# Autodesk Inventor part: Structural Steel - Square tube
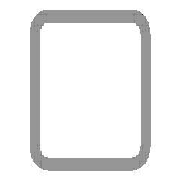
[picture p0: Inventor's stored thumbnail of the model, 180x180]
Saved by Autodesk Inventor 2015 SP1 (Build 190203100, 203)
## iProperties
_CCFamilyMember: 2
_CCFamilyDisplayName: ISO 4019 (Square) - Structural steels - Cold-formed, welded, structural hollow sections
_FrameMemberDoc: Frame Member File
_Version: 15.0.0
_GetPNFromCC: 1
Created: 2011-06
Part Number: Structural Steel - Square tube
Material: Stainless Steel
Document SubType Name: Modeling
Standard: ISO
Designer: Guilherme Augusto Franco de Souza
Standard Revision: Second edition 2001-09-01
Standards Organization: ISO
Language: en-US
Size Designation: 25x25x2
Categories: <MemberInstance><Categories><Category DisplayName="Structural Shapes" InternalName="089c4875-fa83-4c05-b084-43b9cc11f5ed" Mnemonic="GRDR"><CategoryParameter Dis
Stock Number: 25x25x2
Density: 8.08 g/cm^3
Description: ISO 4019 - 25x25x2
Appearance: Steel
G_L: 700,000 mm
G_W: 25,000 mm
G_H: 25,000 mm
+0BBAD034-F051-4CFB-B233-7F78D051060E+CUTDETAIL1: Miter 45,00 deg
+3FA14DB6-D65F-4EF1-82D6-2F48BBAF4B2E+CUTDETAIL2: Miter 45,00 deg
IsCustomPart: 1
Author: Guilherme Augusto Franco de Souza
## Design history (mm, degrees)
node "Start plane"
node "End plane"
sketch "Sketch"
  geometry: L1 (-12.5, -8.5)-(-12.5, 8.5); L2 (-8.5, 12.5)-(8.5, 12.5); L3 (12.5, 8.5)-(12.5, -8.5); L4 (8.5, -12.5)-(-8.5, -12.5); L5 (-8.5, 10.5)-(8.5, 10.5); L6 (10.5, 8.5)-(10.5, -8.5); L7 (8.5, -10.5)-(-8.5, -10.5); L8 (-10.5, -8.5)-(-10.5, 8.5); L9 (0, 18.66)-(0, -18.66) reference; L10 (-18.66, 0)-(18.66, 0) reference; A1 r 4 centre (-8.5, -8.5) between (-12.5, -8.5) and (-8.5, -12.5); A2 r 4 centre (8.5, 8.5) between (12.5, 8.5) and (8.5, 12.5); A3 r 4 centre (-8.5, 8.5) between (-8.5, 12.5) and (-12.5, 8.5); A4 r 4 centre (8.5, -8.5) between (8.5, -12.5) and (12.5, -8.5); A5 r 2 centre (-8.5, 8.5) between (-8.5, 10.5) and (-10.5, 8.5); A6 r 2 centre (8.5, 8.5) between (10.5, 8.5) and (8.5, 10.5); A7 r 2 centre (8.5, -8.5) between (8.5, -10.5) and (10.5, -8.5); A8 r 2 centre (-8.5, -8.5) between (-10.5, -8.5) and (-8.5, -10.5)
  constraints: 16 end point, 16 point on circle, 8 centre point, 8 tangent, 4 parallel, 3 equal radius, 2 perpendicular, 7 other
  dimensions: "d7" = 4 radius of A1 (= G_IR); "d9" = 25 distance between parallel lines of L1 L3 (= G_W); "d11" = 25 distance between parallel lines of L2 L4 (= G_H); "d12" = 2 distance between parallel lines of L3 L6 (= G_T); "d15" = 12.5 distance between parallel lines of L9 L3 (= 0.5 x d9); "d16" = 12.5 distance between parallel lines of L2 L10 (= 0.5 x d11)
extrude "Body" new body sketch "Sketch" stored distance "d3" = 700 (= G_L); taper "d4" = 0 deg
node "Driven Length"
  sketch "Sketch3"
    geometry: L1 (0, 0)-(10, 0) reference
    constraints: 2 end point, 1 horizontal
  workplane "Work Plane3"
  sketch "Sketch4"
    geometry: L1 (-2, 0.141)-(12, 0.141) reference; L2 (-2, 699.859)-(12, 699.859) reference
    dimensions: "d18" = 699.71716 distance between parallel lines of L1 L2 (derived)
workplane "Work Plane4"
split "Split1"
workplane "Work Plane5"
split "Split2"
body "Solid1"
other parameters: "G_W" = 25 [user parameter; used in 1 equation term], "G_H" = 25 [user parameter; used in 1 equation term], "G_T" = 2 [user parameter; used in 1 equation term], "G_IR" = 4 [user parameter; used in 1 equation term], "G_L" = 700 [user parameter; used in 1 equation term], "G_OFFSET_START" = -0.14142 [user parameter; used in 1 equation term], "G_OFFSET_END" = -0.14142 [user parameter; used in 1 equation term], "d13" = 0.14142 (= -G_OFFSET_START), "d14" = 699.85858 (= G_OFFSET_END + B_L), "d17" = 90 deg, "MAS" = 0.136 [user parameter]
